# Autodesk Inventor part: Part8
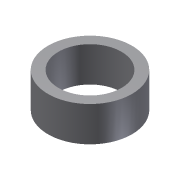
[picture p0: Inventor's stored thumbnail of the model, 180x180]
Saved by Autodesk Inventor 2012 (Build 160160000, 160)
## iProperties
Shininess: 77.0
Length Units: 11269
Angle Units: 11279
Time Units: 11290
Mass Units: 11283
Length Display Precision: 3
Angle Display Precision: 2
Created: 2002-01
Part Number: Part8
Document SubType Name: Modeling
Designer: ***
Density: 1 g/cm^3
Material: Default
Density: 0.0
Volumn: 0.0
Area: 0.0
PropertySet Name: Model Information
Control State: 0
Master: False
Checked Out: False
Author: ***
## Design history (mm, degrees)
sketch "Sketch1"
  geometry: C1 r 30 at (0, 0); C2 r 22.5 at (0, 0)
  constraints: 2 centre point, 1 coincident
  dimensions: "d0" = 60 diameter of C1; "d1" = 45 diameter of C2
extrude "Extrusion1" new body sketch "Sketch1" distance "d2" = 25; taper "d3" = 0 deg
body "Solid1"
